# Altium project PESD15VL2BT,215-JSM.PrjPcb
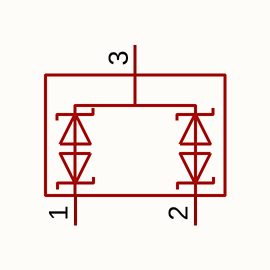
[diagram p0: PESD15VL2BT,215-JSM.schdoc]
1 sheet, 1 parts. Net scope: global (net labels, ports and power ports of the same name join across sheets).

## Sheet PESD15VL2BT,215-JSM.schdoc
size 127 x 101 mm

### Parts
D?  pesd15vl2bt,215-jsm  [SOT-23-3_L2.9-W1.4-P1.90-LS2.5-BR]  (value not drawn)

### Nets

Not connected (* = marked no-connect by the designer): D? 1 2 3

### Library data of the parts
D? = pesd15vl2bt,215-jsm: 极性:双向;反向截止电压(Vrwm):15V;钳位电压:43V;峰值脉冲电流(Ipp):-;峰值脉冲功率(Ppp):200W@8/20us;击穿电压(VBR):17.1V;; Manufacturer: JSMSEMI(杰盛微); AddInBom: yes; ModelId: 9c0df02d6f3e44e889da37f3e5bf5496; ModelTransform: 98.425,114.173,0,0,0,0,0,0,0; Polarity: 双向; Reverse Stand-Off Voltage (Vrwm): 15V; Clamping Voltage: 43V; Voltage - Breakdown: 17.1V; Reverse Leakage Current (Ir): 50nA; Number of Channels: 双路; level of protection: IEC 61000-4-4；IEC 61000-4-2; Type: ESD; Junction Capacitance: 22pF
